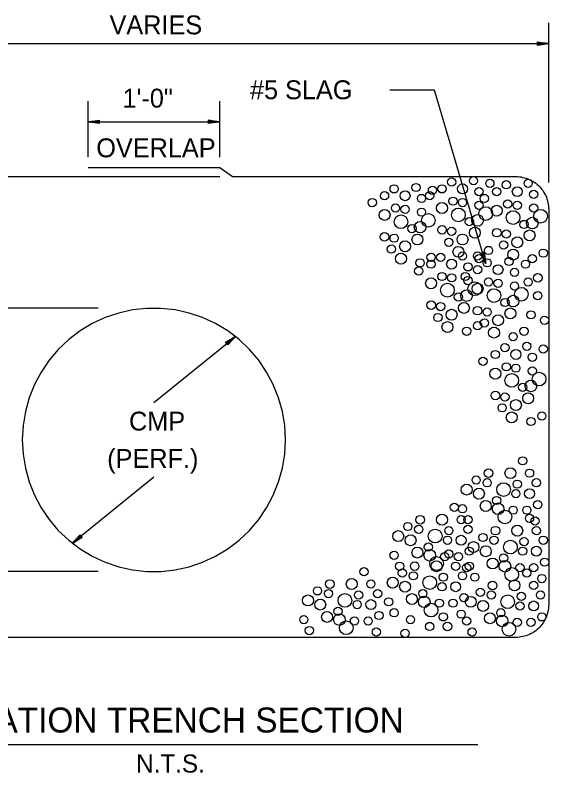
# Model space of a CAD drawing. Extents: x -7.1 to 10, y -5 to 6.
# Drawn here: x 5.369 to 7.238, y -2.419 to 0.233 of the extents above; entities that cross this region are included whole.
import ezdxf

# ---------------------------------------------------------------- set-up
doc = ezdxf.new("R2010")
doc.units = 0
for name, color, linetype in [('Level 11', 7, 'Continuous'), ('Level 14', 7, 'Continuous'), ('Level 6', 7, 'Continuous')]:
    doc.layers.add(name, color=color, linetype=linetype)

msp = doc.modelspace()

# ---------------------------------------------------------------- linework, layer by layer
at = {"layer": 'Level 11'}
for p, q in [((7.2371, -0.3523), (7.2371, 0.2058)), ((4.4721, 0.1333), (7.2371, 0.1333)), ((5.6242, -0.2636), (5.6242, -0.0676)), ((6.085, -0.2636), (6.085, -0.0676)), ((5.6242, -0.1402), (6.085, -0.1402)), ((5.6597, -0.7927), (4.2194, -0.7927)), ((5.8546, -1.1229), (6.1399, -0.8917)), ((5.8546, -1.3842), (5.5693, -1.6154)), ((5.6597, -1.7144), (4.2194, -1.7144)), ((4.8194, -2.3197), (6.9886, -2.3197))]:
    msp.add_line(p, q, dxfattribs=at)
for points in [[(6.6809, -0.0285), (6.836, -0.0285), (7.0163, -0.6356)], [(5.6242, -0.2999), (6.085, -0.2999), (6.1301, -0.3319), (7.1219, -0.3319), (7.1281, -0.3321), (7.1343, -0.3326), (7.1405, -0.3334), (7.1467, -0.3346), (7.1527, -0.3361), (7.1587, -0.3379), (7.1645, -0.3401), (7.1703, -0.3425), (7.1759, -0.3453), (7.1813, -0.3484), (7.1865, -0.3518), (7.1916, -0.3554), (7.1965, -0.3593), (7.2011, -0.3635), (7.2055, -0.3679), (7.2097, -0.3725), (7.2136, -0.3774), (7.2173, -0.3824), (7.2206, -0.3877), (7.2237, -0.3931), (7.2265, -0.3987), (7.2289, -0.4045), (7.2311, -0.4103), (7.2329, -0.4163), (7.2344, -0.4223), (7.2356, -0.4285), (7.2364, -0.4347), (7.2369, -0.4409), (7.2371, -0.4471), (7.2371, -0.4471), (7.2371, -1.8296), (7.2369, -1.8358), (7.2364, -1.8421), (7.2356, -1.8483), (7.2344, -1.8544), (7.2329, -1.8604), (7.2311, -1.8664), (7.2289, -1.8723), (7.2264, -1.878), (7.2237, -1.8836), (7.2206, -1.889), (7.2172, -1.8943), (7.2136, -1.8993), (7.2097, -1.9042), (7.2055, -1.9088), (7.2011, -1.9133), (7.1965, -1.9174), (7.1916, -1.9213), (7.1865, -1.925), (7.1813, -1.9283), (7.1759, -1.9314), (7.1703, -1.9342), (7.1645, -1.9366), (7.1587, -1.9388), (7.1527, -1.9406), (7.1467, -1.9421), (7.1405, -1.9433), (7.1343, -1.9441), (7.1281, -1.9446), (7.1219, -1.9448), (7.1219, -1.9448), (4.5873, -1.9448)], [(4.5873, -0.3319), (6.085, -0.3319)], [(6.3154, -1.2536), (6.3127, -1.2037), (6.3046, -1.1545), (6.2913, -1.1064), (6.2728, -1.0601), (6.2495, -1.016), (6.2215, -0.9747), (6.1892, -0.9366), (6.1529, -0.9023), (6.1132, -0.8721), (6.0704, -0.8464), (6.0252, -0.8255), (5.9779, -0.8095), (5.9291, -0.7988), (5.8795, -0.7934), (5.8296, -0.7934), (5.78, -0.7988), (5.7313, -0.8095), (5.684, -0.8255), (5.6387, -0.8464), (5.596, -0.8721), (5.5563, -0.9023), (5.52, -0.9366), (5.4877, -0.9747), (5.4597, -1.016), (5.4363, -1.0601), (5.4179, -1.1064), (5.4045, -1.1545), (5.3965, -1.2037), (5.3938, -1.2536), (5.3938, -1.2536), (5.3965, -1.3034), (5.4045, -1.3526), (5.4179, -1.4007), (5.4363, -1.4471), (5.4597, -1.4912), (5.4877, -1.5324), (5.52, -1.5705), (5.5563, -1.6048), (5.596, -1.635), (5.6387, -1.6607), (5.684, -1.6817), (5.7313, -1.6976), (5.78, -1.7083), (5.8296, -1.7137), (5.8795, -1.7137), (5.9291, -1.7083), (5.9779, -1.6976), (6.0252, -1.6817), (6.0704, -1.6607), (6.1132, -1.635), (6.1529, -1.6048), (6.1892, -1.5705), (6.2215, -1.5324), (6.2495, -1.4912), (6.2728, -1.4471), (6.2913, -1.4007), (6.3046, -1.3526), (6.3127, -1.3034), (6.3154, -1.2536), (6.3154, -1.2536)]]:
    msp.add_lwpolyline(points, dxfattribs=at)
for centre, radius in [((6.897, -0.3511), 0.0144), ((6.9737, -0.3463), 0.0144), ((7.0311, -0.3558), 0.0144), ((7.1652, -0.3558), 0.0144), ((6.6958, -0.375), 0.0144), ((6.7725, -0.3702), 0.0144), ((6.83, -0.3798), 0.0144), ((6.8635, -0.375), 0.0144), ((6.9353, -0.375), 0.0173), ((6.9928, -0.3846), 0.0144), ((7.0551, -0.3846), 0.0144), ((7.0886, -0.3606), 0.0144), ((7.1269, -0.3846), 0.0173), ((6.6623, -0.399), 0.0144), ((6.7342, -0.399), 0.0173), ((6.7916, -0.4085), 0.0144), ((6.8204, -0.399), 0.0144), ((7.012, -0.4085), 0.0144), ((7.1844, -0.3942), 0.0144), ((6.6192, -0.4229), 0.0144), ((6.8635, -0.4421), 0.0192), ((6.9018, -0.4181), 0.0144), ((6.9353, -0.4229), 0.0144), ((6.9928, -0.4325), 0.0144), ((7.0934, -0.4277), 0.0144), ((7.1269, -0.4325), 0.0144), ((6.6623, -0.466), 0.0192), ((6.7006, -0.4421), 0.0144), ((6.7342, -0.4469), 0.0144), ((6.7916, -0.4564), 0.0144), ((6.921, -0.466), 0.0239), ((7.0168, -0.4612), 0.0239), ((7.0551, -0.4516), 0.0192), ((7.1844, -0.4421), 0.0144), ((7.2084, -0.4708), 0.0239), ((6.7198, -0.49), 0.0239), ((6.8156, -0.4852), 0.0239), ((6.9593, -0.49), 0.0144), ((6.988, -0.4852), 0.0203), ((7.1126, -0.4756), 0.0239), ((7.1796, -0.4948), 0.0203), ((6.7581, -0.5139), 0.0144), ((6.7868, -0.5091), 0.0203), ((6.8635, -0.5187), 0.0151), ((7.1509, -0.4995), 0.0144), ((6.6623, -0.5426), 0.0151), ((6.897, -0.5235), 0.0144), ((6.9784, -0.5283), 0.0192), ((7.0551, -0.5283), 0.0151), ((7.0886, -0.5331), 0.0144), ((7.17, -0.5379), 0.0192), ((6.6958, -0.5474), 0.0144), ((6.7773, -0.5522), 0.0192), ((6.8874, -0.5618), 0.0144), ((6.9353, -0.5522), 0.0192), ((7.1269, -0.5618), 0.0192), ((6.6863, -0.5858), 0.0144), ((6.7342, -0.5762), 0.0192), ((6.921, -0.5953), 0.0192), ((7.0263, -0.5905), 0.0144), ((7.079, -0.5714), 0.0144), ((6.7198, -0.6193), 0.0192), ((6.8252, -0.6145), 0.0144), ((6.8587, -0.6145), 0.0144), ((6.9353, -0.6097), 0.0144), ((6.988, -0.6097), 0.0144), ((6.9928, -0.6193), 0.0144), ((7.1126, -0.6049), 0.0192), ((7.1796, -0.6193), 0.0144), ((7.2179, -0.6001), 0.0144), ((6.7868, -0.6337), 0.0144), ((6.8252, -0.6384), 0.0144), ((6.897, -0.6384), 0.0173), ((6.9545, -0.648), 0.0144), ((7.0215, -0.6337), 0.0144), ((7.0982, -0.6289), 0.0144), ((7.1557, -0.6384), 0.0144), ((6.7821, -0.6624), 0.0144), ((6.988, -0.6576), 0.0144), ((7.0599, -0.6576), 0.0173), ((7.1173, -0.6672), 0.0144), ((6.8252, -0.7055), 0.0192), ((6.8635, -0.6816), 0.0144), ((6.897, -0.6863), 0.0144), ((6.9449, -0.6816), 0.0144), ((6.9545, -0.6959), 0.0144), ((7.0263, -0.7007), 0.0144), ((7.1652, -0.7007), 0.0144), ((7.1988, -0.6863), 0.0151), ((6.8826, -0.7295), 0.024), ((6.9784, -0.7247), 0.024), ((6.988, -0.7247), 0.0192), ((7.0599, -0.7055), 0.0144), ((7.1173, -0.7151), 0.0144), ((6.921, -0.7534), 0.0144), ((6.9497, -0.7486), 0.0203), ((7.0455, -0.7486), 0.024), ((7.1413, -0.7438), 0.024), ((7.1988, -0.7486), 0.0144), ((6.8252, -0.7821), 0.0151), ((7.0838, -0.7726), 0.0144), ((7.1126, -0.7678), 0.0203), ((6.8587, -0.7869), 0.0144), ((6.9401, -0.7917), 0.0192), ((6.988, -0.8013), 0.0151), ((7.0215, -0.8061), 0.0144), ((7.103, -0.8109), 0.0192), ((6.8491, -0.8253), 0.0144), ((6.897, -0.8157), 0.0192), ((7.0599, -0.8348), 0.0192), ((7.1748, -0.8157), 0.0144), ((7.2227, -0.8348), 0.0144), ((6.8826, -0.8588), 0.0192), ((6.988, -0.854), 0.0144), ((7.012, -0.8444), 0.0144), ((6.9497, -0.8732), 0.0144), ((7.0455, -0.8779), 0.0192), ((7.1509, -0.8732), 0.0144), ((7.1126, -0.8923), 0.0144), ((7.0838, -0.9306), 0.0144), ((7.1605, -0.9258), 0.0144), ((7.2179, -0.9354), 0.0144), ((7.0503, -0.9546), 0.0144), ((7.1221, -0.9546), 0.0173), ((7.1796, -0.9642), 0.0144), ((7.0072, -0.9785), 0.0144), ((7.0503, -1.0216), 0.0192), ((7.0886, -0.9977), 0.0144), ((7.1221, -1.0025), 0.0144), ((7.1796, -1.0121), 0.0144), ((7.1078, -1.0456), 0.0239), ((7.2036, -1.0408), 0.0239), ((7.1461, -1.0695), 0.0144), ((7.1748, -1.0647), 0.0203), ((7.0503, -1.0983), 0.0151), ((7.0838, -1.1031), 0.0144), ((7.1221, -1.1318), 0.0192), ((7.1652, -1.1079), 0.0192), ((7.0742, -1.1414), 0.0144), ((7.1078, -1.1749), 0.0192), ((7.2131, -1.1701), 0.0144), ((7.1748, -1.1893), 0.0144), ((7.1461, -1.3269), 0.0144), ((7.103, -1.37), 0.0192), ((7.0263, -1.37), 0.0151), ((7.17, -1.37), 0.0144), ((6.9832, -1.394), 0.0144), ((7.0215, -1.4036), 0.0144), ((7.079, -1.4275), 0.0239), ((7.1269, -1.4084), 0.0144), ((7.194, -1.4036), 0.0144), ((6.9497, -1.4275), 0.0192), ((6.9928, -1.4419), 0.0192), ((7.1221, -1.4419), 0.0144), ((7.17, -1.4419), 0.0173), ((7.0551, -1.4658), 0.0144), ((6.9066, -1.4898), 0.0144), ((6.9353, -1.4946), 0.0144), ((7.0168, -1.485), 0.0192), ((7.0599, -1.4946), 0.0203), ((7.1126, -1.4994), 0.0144), ((7.1605, -1.4994), 0.0144), ((7.1988, -1.4802), 0.0144), ((7.0838, -1.5233), 0.0239), ((6.7868, -1.5329), 0.0151), ((6.8635, -1.5329), 0.0192), ((6.9305, -1.5329), 0.0144), ((6.9545, -1.5329), 0.0144), ((7.17, -1.5281), 0.0144), ((7.1892, -1.5377), 0.0144), ((6.7437, -1.5568), 0.0144), ((6.7821, -1.5664), 0.0144), ((6.8874, -1.5712), 0.0144), ((6.9545, -1.5664), 0.0144), ((7.0503, -1.5712), 0.0151), ((7.1269, -1.5712), 0.0192), ((7.194, -1.5712), 0.0144), ((6.7102, -1.5904), 0.0192), ((6.7533, -1.6047), 0.0192), ((6.8395, -1.5904), 0.024), ((6.8826, -1.6047), 0.0144), ((6.9305, -1.6047), 0.0173), ((7.0072, -1.5952), 0.0144), ((7.0455, -1.6047), 0.0144), ((7.2179, -1.6047), 0.0144), ((6.8156, -1.6287), 0.0144), ((6.9737, -1.6287), 0.0192), ((7.103, -1.6287), 0.0239), ((7.1509, -1.6095), 0.0144), ((6.6958, -1.6574), 0.0144), ((6.7773, -1.6478), 0.0192), ((6.8204, -1.6574), 0.0203), ((6.8874, -1.6526), 0.0144), ((6.9593, -1.6431), 0.0144), ((7.0168, -1.6431), 0.0192), ((7.1461, -1.6431), 0.0144), ((7.194, -1.6431), 0.0173), ((6.8443, -1.6862), 0.024), ((6.8731, -1.6622), 0.0144), ((6.921, -1.6622), 0.0144), ((7.0407, -1.6862), 0.0192), ((7.079, -1.667), 0.0144), ((7.2227, -1.6814), 0.0144), ((6.715, -1.6957), 0.0144), ((6.7677, -1.6957), 0.0151), ((6.8443, -1.6957), 0.0192), ((6.9114, -1.6957), 0.0144), ((6.9497, -1.7005), 0.0144), ((6.9593, -1.6957), 0.0144), ((7.0838, -1.6957), 0.0203), ((7.1365, -1.7005), 0.0144), ((7.1844, -1.7005), 0.0144), ((6.5905, -1.7149), 0.0144), ((6.7246, -1.7197), 0.0144), ((6.7629, -1.7293), 0.0144), ((6.8683, -1.7341), 0.0144), ((6.9353, -1.7293), 0.0144), ((6.9784, -1.7341), 0.0144), ((7.1078, -1.7245), 0.0239), ((7.1605, -1.7197), 0.0144), ((6.4707, -1.758), 0.0151), ((6.5474, -1.758), 0.0192), ((6.6144, -1.758), 0.0144), ((6.691, -1.7532), 0.0192), ((6.7342, -1.7676), 0.0192), ((6.8204, -1.7532), 0.024), ((7.0407, -1.7628), 0.0151), ((7.1173, -1.7628), 0.0192), ((7.1844, -1.7628), 0.0144), ((7.2131, -1.7389), 0.0144), ((6.4276, -1.782), 0.0144), ((6.8635, -1.7676), 0.0144), ((6.9114, -1.7676), 0.0173), ((6.9976, -1.7868), 0.0144), ((6.3941, -1.8155), 0.0192), ((6.4659, -1.7915), 0.0144), ((6.5234, -1.8155), 0.0239), ((6.5713, -1.7963), 0.0144), ((6.6384, -1.7915), 0.0144), ((6.7581, -1.8107), 0.0192), ((6.8012, -1.8203), 0.0203), ((6.7964, -1.7915), 0.0144), ((6.9401, -1.8059), 0.0144), ((6.9641, -1.8203), 0.0192), ((7.0359, -1.7963), 0.0144), ((7.0934, -1.8203), 0.0239), ((7.1413, -1.8011), 0.0144), ((7.2084, -1.7963), 0.0144), ((6.4372, -1.8299), 0.0192), ((6.5665, -1.8299), 0.0144), ((6.6144, -1.8299), 0.0173), ((6.6767, -1.8203), 0.0144), ((6.8252, -1.849), 0.024), ((6.8539, -1.8251), 0.0144), ((6.9018, -1.8251), 0.0144), ((7.0072, -1.8347), 0.0192), ((7.1365, -1.8347), 0.0144), ((7.1844, -1.8347), 0.0173), ((6.4611, -1.873), 0.0192), ((6.4995, -1.8538), 0.0144), ((6.6431, -1.8682), 0.0144), ((6.6958, -1.8586), 0.0144), ((6.9305, -1.8634), 0.0144), ((7.0694, -1.8586), 0.0144), ((6.3797, -1.8826), 0.0144), ((6.5042, -1.8826), 0.0203), ((6.5569, -1.8873), 0.0144), ((6.6048, -1.8873), 0.0144), ((6.7533, -1.8826), 0.0144), ((6.8683, -1.873), 0.0144), ((6.9497, -1.8873), 0.0144), ((7.0311, -1.8778), 0.0192), ((7.0742, -1.8873), 0.0203), ((7.1269, -1.8921), 0.0144), ((7.1748, -1.8921), 0.0144), ((7.2131, -1.873), 0.0144), ((6.3989, -1.9209), 0.0144), ((6.5282, -1.9113), 0.0239), ((6.8204, -1.9065), 0.0144), ((6.8826, -1.9065), 0.0151), ((7.0982, -1.9161), 0.0239), ((6.6336, -1.9257), 0.0144), ((6.7342, -1.9304), 0.0144), ((6.9689, -1.9257), 0.0144)]:
    msp.add_circle(centre, radius, dxfattribs=at)
at = {"layer": 'Level 6'}
for p, q in [((7.1979, 0.1274), (7.1979, 0.1397)), ((7.1979, 0.1397), (7.2376, 0.1332)), ((7.2376, 0.1333), (7.1979, 0.1373)), ((7.1979, 0.1373), (7.1979, 0.1313)), ((7.1979, 0.1333), (7.1979, 0.1353)), ((7.1979, 0.1353), (7.2376, 0.1333)), ((7.1979, 0.1294), (7.2376, 0.1333)), ((7.2376, 0.1333), (7.1979, 0.1333)), ((7.1979, 0.1313), (7.2356, 0.1333)), ((7.2374, 0.1331), (7.1979, 0.1274)), ((5.6633, -0.1363), (5.6237, -0.1402)), ((5.6634, -0.1466), (5.6237, -0.1401)), ((5.6237, -0.1402), (5.6633, -0.1402)), ((5.6633, -0.1422), (5.6237, -0.1402)), ((5.6237, -0.1402), (5.6633, -0.1442)), ((5.6239, -0.14), (5.6634, -0.1343)), ((5.6633, -0.1382), (5.6256, -0.1402)), ((5.6633, -0.1442), (5.6633, -0.1382)), ((5.6633, -0.1402), (5.6633, -0.1422)), ((5.6634, -0.1343), (5.6634, -0.1466)), ((6.0458, -0.1461), (6.0458, -0.1338)), ((6.0458, -0.1338), (6.0854, -0.1402)), ((6.0855, -0.1401), (6.0458, -0.1361)), ((6.0458, -0.1361), (6.0458, -0.1421)), ((6.0458, -0.1401), (6.0458, -0.1381)), ((6.0458, -0.1381), (6.0855, -0.1401)), ((6.0458, -0.1441), (6.0855, -0.1401)), ((6.0855, -0.1401), (6.0458, -0.1401)), ((6.0458, -0.1421), (6.0835, -0.1401)), ((6.0853, -0.1404), (6.0458, -0.1461)), ((6.9995, -0.5997), (7.0113, -0.5962)), ((7.0162, -0.6359), (6.9995, -0.5997)), ((7.0014, -0.5991), (7.0165, -0.636)), ((7.009, -0.5969), (7.0033, -0.5986)), ((7.0033, -0.5986), (7.0159, -0.6341)), ((7.0052, -0.598), (7.0071, -0.5974)), ((7.0165, -0.636), (7.0052, -0.598)), ((7.0071, -0.5974), (7.0165, -0.636)), ((7.0165, -0.636), (7.009, -0.5969)), ((7.0113, -0.5962), (7.0164, -0.636)), ((6.1055, -0.9114), (6.1403, -0.8915)), ((6.1403, -0.8914), (6.107, -0.9133)), ((6.1082, -0.9148), (6.1403, -0.8914)), ((6.1403, -0.8914), (6.1095, -0.9163)), ((6.1107, -0.9179), (6.1388, -0.8926)), ((6.112, -0.9194), (6.1403, -0.8914)), ((6.1403, -0.8917), (6.1132, -0.921)), ((6.1132, -0.921), (6.1055, -0.9114)), ((6.107, -0.9133), (6.1107, -0.9179)), ((6.1095, -0.9163), (6.1082, -0.9148)), ((5.5689, -1.6155), (5.596, -1.5862)), ((5.5972, -1.5877), (5.5689, -1.6158)), ((5.5689, -1.6158), (5.5997, -1.5908)), ((5.5985, -1.5893), (5.5704, -1.6145)), ((5.596, -1.5862), (5.6038, -1.5957)), ((5.6022, -1.5939), (5.5985, -1.5893)), ((5.5997, -1.5908), (5.601, -1.5924)), ((5.601, -1.5924), (5.5689, -1.6158)), ((5.5689, -1.6158), (5.6022, -1.5939)), ((5.6038, -1.5957), (5.5689, -1.6157))]:
    msp.add_line(p, q, dxfattribs=at)

# ---------------------------------------------------------------- texts
at = {"layer": 'Level 11'}
for s, height, p in [('VARIES', 0.06613, (5.6993, 0.1659)), ('#5 SLAG', 0.06613, (6.1911, -0.0612)), ('1\'-0"', 0.06613, (5.7449, -0.0905)), ('OVERLAP', 0.06613, (5.6529, -0.2644)), ('CMP', 0.06613, (5.7676, -1.2209)), ('(PERF.)', 0.06613, (5.6911, -1.3516)), ('EXFILTRATION TRENCH SECTION', 0.087469, (4.8189, -2.2777))]:
    msp.add_text(s, height=height, dxfattribs=at).set_placement(p)
at = {"layer": 'Level 14'}
msp.add_text('N.T.S.', height=0.06348, dxfattribs=at).set_placement((5.7925, -2.418))

doc.saveas('drawing.dxf')
